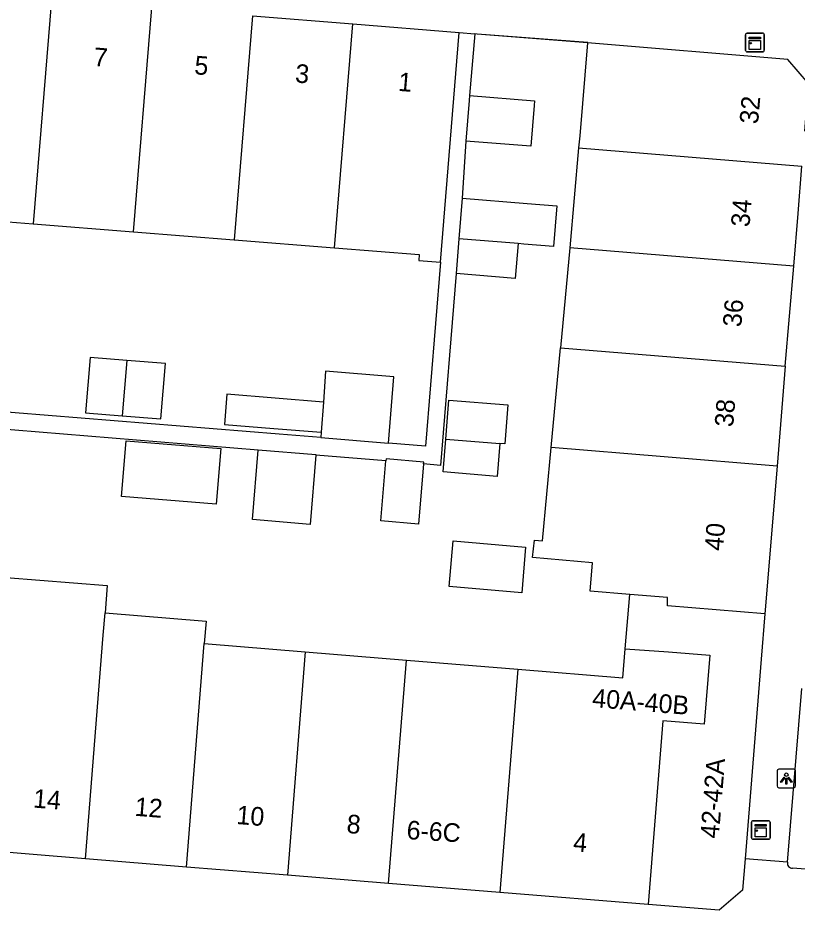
# Model space of a CAD drawing. Extents: x 159961 to 160856, y 382704 to 383353.
# Drawn here: x 160535.54 to 160577.41, y 383142.38 to 383190.3 of the extents above; entities that cross this region are included whole.
import ezdxf

# ---------------------------------------------------------------- set-up
doc = ezdxf.new("R2010")
doc.units = 0
for name, color, linetype in [('IMGEO_Kast', 7, 'Continuous'), ('IMGEO_Lichtpunt', 7, 'Continuous'), ('IMGEO_Muur', 7, 'Continuous'), ('IMGEO_Pand', 7, 'Continuous'), ('IMGEO_Pand_nummerreeks', 7, 'Continuous'), ('IMGEO_Voetpad_open', 7, 'Continuous')]:
    doc.layers.add(name, color=color, linetype=linetype)

msp = doc.modelspace()

# ---------------------------------------------------------------- linework, layer by layer
at = {"layer": 'IMGEO_Kast'}
for p, q in [((160574.634, 383188.548), (160574.634, 383189.389)), ((160574.634, 383189.389), (160574.634, 383188.548)), ((160574.709, 383189.473), (160575.55, 383189.473)), ((160575.55, 383189.473), (160574.709, 383189.473)), ((160575.634, 383189.398), (160575.634, 383188.557)), ((160575.634, 383188.557), (160575.634, 383189.398)), ((160575.559, 383188.473), (160574.718, 383188.473)), ((160574.718, 383188.473), (160575.559, 383188.473)), ((160574.955, 383146.259), (160574.955, 383147.1)), ((160574.955, 383147.1), (160574.955, 383146.259)), ((160575.03, 383147.184), (160575.871, 383147.184)), ((160575.871, 383147.184), (160575.03, 383147.184)), ((160575.955, 383147.109), (160575.955, 383146.268)), ((160575.955, 383146.268), (160575.955, 383147.109)), ((160575.88, 383146.184), (160575.039, 383146.184)), ((160575.039, 383146.184), (160575.88, 383146.184))]:
    msp.add_line(p, q, dxfattribs=at)
for points in [[(160574.829, 383189.263), (160575.429, 383189.263), (160575.429, 383189.178), (160574.829, 383189.178), (160574.829, 383189.263)], [(160574.829, 383189.088), (160575.429, 383189.088), (160575.429, 383188.599), (160574.829, 383188.599), (160574.829, 383189.088)], [(160575.15, 383146.974), (160575.75, 383146.974), (160575.75, 383146.889), (160575.15, 383146.889), (160575.15, 383146.974)], [(160575.15, 383146.799), (160575.75, 383146.799), (160575.75, 383146.31), (160575.15, 383146.31), (160575.15, 383146.799)]]:
    msp.add_lwpolyline(points, dxfattribs=at)
for centre in [(160574.913, 383188.937), (160575.234, 383146.648)]:
    msp.add_circle(centre, 0.0377, dxfattribs=at)
for centre, start, end in [((160574.712, 383189.395), 92.4484, 184.2845), ((160574.712, 383189.395), 92.4484, 184.2845), ((160575.556, 383189.395), 2.4484, 94.2845), ((160575.556, 383189.395), 2.4484, 94.2845), ((160574.712, 383188.551), 182.4484, 274.2845), ((160574.712, 383188.551), 182.4484, 274.2845), ((160575.556, 383188.551), 272.4484, 4.2845), ((160575.556, 383188.551), 272.4484, 4.2845), ((160575.033, 383147.106), 92.4484, 184.2845), ((160575.033, 383147.106), 92.4484, 184.2845), ((160575.877, 383147.106), 2.4484, 94.2845), ((160575.877, 383147.106), 2.4484, 94.2845), ((160575.033, 383146.262), 182.4484, 274.2845), ((160575.033, 383146.262), 182.4484, 274.2845), ((160575.877, 383146.262), 272.4484, 4.2845), ((160575.877, 383146.262), 272.4484, 4.2845)]:
    msp.add_arc(centre, 0.0779, start, end, dxfattribs=at)
at = {"layer": 'IMGEO_Lichtpunt'}
for p, q in [((160576.326, 383149.856), (160576.326, 383149.049)), ((160576.326, 383149.856), (160576.326, 383149.049)), ((160577.228, 383149.951), (160576.42, 383149.951)), ((160577.228, 383149.951), (160576.42, 383149.951)), ((160577.322, 383149.049), (160577.322, 383149.856)), ((160577.322, 383149.049), (160577.322, 383149.856)), ((160576.42, 383148.955), (160577.228, 383148.955)), ((160576.42, 383148.955), (160577.228, 383148.955))]:
    msp.add_line(p, q, dxfattribs=at)
for points in [[(160576.7, 383149.52), (160576.739, 383149.492), (160576.551, 383149.23), (160576.513, 383149.257), (160576.7, 383149.52)], [(160576.802, 383149.472), (160576.849, 383149.472), (160576.849, 383149.15), (160576.802, 383149.15), (160576.802, 383149.472)], [(160576.912, 383149.492), (160576.95, 383149.519), (160577.137, 383149.257), (160577.098, 383149.229), (160576.912, 383149.492)]]:
    msp.add_lwpolyline(points, dxfattribs=at)
msp.add_circle((160576.825, 383149.654), 0.0994, dxfattribs=at)
for centre, start, end in [((160576.42, 383149.856), 90, 180), ((160576.42, 383149.856), 90, 180), ((160577.228, 383149.856), 0, 90), ((160577.228, 383149.856), 0, 90), ((160576.42, 383149.049), 180, 270), ((160576.42, 383149.049), 180, 270), ((160577.228, 383149.049), 270, 0), ((160577.228, 383149.049), 270, 360)]:
    msp.add_arc(centre, 0.0946, start, end, dxfattribs=at)
at = {"layer": 'IMGEO_Muur'}
msp.add_lwpolyline([(160566.163, 383188.979), (160560.216, 383189.428)], dxfattribs=at)
at = {"layer": 'IMGEO_Pand'}
for points in [[(160537.343, 383191.275), (160536.362, 383179.24)], [(160541.76, 383178.809), (160542.741, 383190.841)], [(160548.138, 383190.406), (160547.158, 383178.378)], [(160548.138, 383190.406), (160553.535, 383189.972)], [(160552.556, 383177.948), (160553.535, 383189.972)], [(160553.535, 383189.972), (160559.239, 383189.512)], [(160558.242, 383177.186), (160559.239, 383189.512)], [(160566.136, 383188.953), (160565.723, 383183.97), (160565.665, 383183.319)], [(160577.812, 383184.207), (160578.016, 383186.764), (160576.912, 383188.059), (160566.136, 383188.953)], [(160559.811, 383186.122), (160563.3, 383185.837), (160563.279, 383185.582), (160563.101, 383183.399), (160559.612, 383183.684)], [(160559.811, 383186.122), (160559.79, 383185.867), (160559.612, 383183.684)], [(160565.665, 383183.319), (160565.194, 383177.951)], [(160565.665, 383183.319), (160577.664, 383182.341)], [(160577.22, 383176.97), (160577.46, 383179.786), (160577.664, 383182.341)], [(160559.415, 383180.621), (160559.237, 383178.438)], [(160559.415, 383180.621), (160562.904, 383180.336), (160564.5, 383180.206), (160564.322, 383178.023), (160562.726, 383178.153), (160562.415, 383178.178)], [(160530.965, 383179.671), (160536.362, 383179.24)], [(160536.362, 383179.24), (160541.76, 383178.809)], [(160541.76, 383178.809), (160547.158, 383178.378)], [(160547.158, 383178.378), (160552.556, 383177.948)], [(160559.237, 383178.438), (160559.084, 383176.563)], [(160562.415, 383178.178), (160562.262, 383176.304), (160559.084, 383176.563)], [(160562.415, 383178.178), (160562.203, 383178.196), (160559.237, 383178.438)], [(160552.556, 383177.948), (160557.094, 383177.585), (160557.078, 383177.266), (160558.242, 383177.186)], [(160565.194, 383177.951), (160564.691, 383172.585)], [(160577.22, 383176.97), (160565.194, 383177.951)], [(160576.762, 383171.601), (160577.22, 383176.97)], [(160564.189, 383167.221), (160564.691, 383172.585)], [(160564.691, 383172.585), (160576.762, 383171.601)], [(160541.392, 383171.902), (160539.415, 383172.063), (160539.173, 383169.09), (160541.15, 383168.929)], [(160541.392, 383171.902), (160541.15, 383168.929)], [(160541.15, 383168.929), (160543.225, 383168.76), (160543.467, 383171.732), (160541.392, 383171.902)], [(160576.762, 383171.601), (160576.324, 383166.23)], [(160555.45, 383167.458), (160555.739, 383171.022), (160552.074, 383171.319), (160551.954, 383169.663)], [(160551.954, 383169.663), (160546.767, 383170.086), (160546.635, 383168.466), (160549.282, 383168.25), (160551.837, 383168.042)], [(160551.954, 383169.663), (160551.837, 383168.042)], [(160558.525, 383167.675), (160558.695, 383169.767), (160561.87, 383169.507), (160561.699, 383167.416), (160561.431, 383167.438)], [(160551.837, 383168.042), (160551.816, 383167.753)], [(160546.435, 383167.166), (160546.193, 383164.187), (160541.113, 383164.601), (160541.356, 383167.58), (160546.435, 383167.166)], [(160551.816, 383167.753), (160555.45, 383167.458)], [(160561.431, 383167.438), (160561.287, 383165.675), (160558.381, 383165.912), (160558.525, 383167.675)], [(160558.525, 383167.675), (160561.431, 383167.438)], [(160551.553, 383166.817), (160551.25, 383163.096), (160548.138, 383163.35), (160548.441, 383167.073)], [(160548.441, 383167.073), (160548.444, 383167.105), (160551.556, 383166.852), (160551.553, 383166.817)], [(160568.417, 383159.338), (160566.292, 383159.51), (160566.416, 383161.039), (160563.186, 383161.319), (160563.292, 383162.243), (160563.719, 383162.208), (160564.189, 383167.221)], [(160576.324, 383166.23), (160564.189, 383167.221)], [(160557.336, 383166.341), (160557.345, 383166.44), (160555.319, 383166.616), (160555.31, 383166.508)], [(160557.336, 383166.341), (160557.057, 383163.112), (160555.031, 383163.288), (160555.31, 383166.508)], [(160576.324, 383166.23), (160575.677, 383158.296)], [(160562.817, 383161.871), (160562.606, 383159.427), (160558.712, 383159.765), (160558.924, 383162.209), (160562.817, 383161.871)], [(160534.702, 383157.582), (160534.915, 383160.246), (160540.33, 383159.813), (160540.22, 383158.346)], [(160568.171, 383156.406), (160568.417, 383159.338)], [(160575.677, 383158.296), (160570.437, 383158.72), (160570.435, 383159.175), (160568.417, 383159.338)], [(160539.17, 383145.135), (160540.13, 383157.138), (160540.22, 383158.346)], [(160540.22, 383158.346), (160545.653, 383157.903), (160545.556, 383156.695)], [(160575.677, 383158.296), (160575.477, 383155.851), (160574.61, 383145.13)], [(160544.596, 383144.696), (160545.556, 383156.695)], [(160545.556, 383156.695), (160550.983, 383156.251)], [(160550.983, 383156.251), (160550.024, 383144.257)], [(160550.983, 383156.251), (160556.41, 383155.808)], [(160562.391, 383155.319), (160568.041, 383154.857), (160568.171, 383156.406)], [(160568.171, 383156.406), (160570.494, 383156.253), (160572.707, 383156.074), (160572.408, 383152.374), (160570.195, 383152.553), (160569.397, 383142.688)], [(160555.451, 383143.817), (160556.41, 383155.808)], [(160556.41, 383155.808), (160562.391, 383155.319)], [(160562.391, 383155.319), (160561.432, 383143.333)], [(160539.17, 383145.135), (160533.742, 383145.575)], [(160544.596, 383144.696), (160539.17, 383145.135)], [(160574.61, 383145.13), (160574.474, 383143.451), (160573.213, 383142.379), (160569.397, 383142.688)], [(160550.024, 383144.257), (160544.596, 383144.696)], [(160555.451, 383143.817), (160550.024, 383144.257)], [(160561.432, 383143.333), (160555.451, 383143.817)], [(160569.397, 383142.688), (160561.432, 383143.333)]]:
    msp.add_lwpolyline(points, dxfattribs=at)
at = {"layer": 'IMGEO_Voetpad_open'}
for points in [[(160559.239, 383189.512), (160560.097, 383189.438)], [(160560.097, 383189.438), (160559.811, 383186.122)], [(160566.136, 383188.953), (160560.216, 383189.428), (160560.097, 383189.438)], [(160559.612, 383183.684), (160559.415, 383180.621)], [(160558.242, 383177.186), (160557.442, 383167.296), (160555.45, 383167.458)], [(160559.084, 383176.563), (160558.245, 383166.266), (160557.336, 383166.341)], [(160551.816, 383167.753), (160549.579, 383167.935), (160530.055, 383169.521)], [(160548.441, 383167.073), (160527.513, 383168.796)], [(160555.31, 383166.508), (160551.553, 383166.817)], [(160576.888, 383144.956), (160577.659, 383154.277)], [(160576.888, 383144.956), (160574.61, 383145.13)], [(160580.704, 383144.357), (160577.161, 383144.638)]]:
    msp.add_lwpolyline(points, dxfattribs=at)
msp.add_arc((160577.147, 383144.902), 0.264, 168.2058, 273.0858, dxfattribs=at)

# ---------------------------------------------------------------- texts
at = {"layer": 'IMGEO_Pand_nummerreeks'}
for s, rotation, p in [('7', 355.343, (160539.579, 383187.714)), ('5', 355.343, (160544.995, 383187.273)), ('3', 355.343, (160550.411, 383186.831)), ('1', 355.343, (160555.942, 383186.38)), ('32', 85.0499, (160575.302, 383184.568)), ('34', 85.3363, (160574.841, 383179.039)), ('36', 85.3363, (160574.403, 383173.668)), ('38', 85.3362, (160573.965, 383168.299)), ('40', 85.3363, (160573.422, 383161.648)), ('40A-40B', 355.3894, (160566.371, 383153.285)), ('42-42A', 85.3764, (160573.192, 383146.205)), ('14', 355.3705, (160536.332, 383147.893)), ('12', 355.3705, (160541.789, 383147.452)), ('10', 355.3709, (160547.255, 383147.009)), ('8', 355.3709, (160553.175, 383146.53)), ('6-6C', 356.5526, (160556.404, 383146.195)), ('4', 355.3709, (160565.344, 383145.545))]:
    msp.add_text(s, height=1, rotation=rotation, dxfattribs=at).set_placement(p)

doc.saveas('drawing.dxf')
